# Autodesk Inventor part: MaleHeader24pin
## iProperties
Shininess: 64.0
Length Units: 11272
Angle Units: 11279
Time Units: 11290
Mass Units: 11286
Length Display Precision: 3
Angle Display Precision: 2
Compacted: True
Part Number: MaleHeader24pin
Document SubType Name: Modeling
Created: 2006-08
Designer: jpalmisano
Manufacturer: Standard
Standards Organization: Custom
Density: 0.0
Volumn: 0.0
Area: 0.0
PropertySet Name: Model Information
Control State: 0
Master: False
Checked Out: False
Author: jpalmisano
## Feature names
1. Extrusion1
2. Extrusion2
